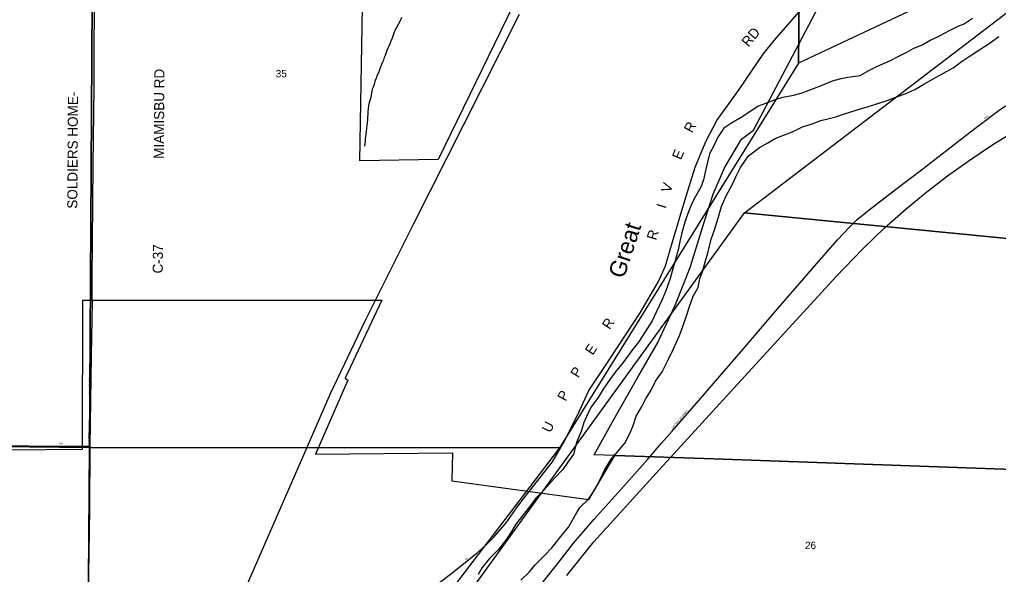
# Model space of a CAD drawing. Extents: x 1312308 to 1684953, y 460642 to 865172.
# Drawn here: x 1464004 to 1471284, y 608140 to 612264 of the extents above; entities that cross this region are included whole.
import ezdxf

# ---------------------------------------------------------------- set-up
doc = ezdxf.new("R2010")
doc.units = 0
for name, color, linetype in [('GM_X_City_Street', 7, 'Continuous'), ('GM_X_City_Street_Text', 7, 'Continuous'), ('GM_X_Corporation', 7, 'Continuous'), ('GM_X_County_Road', 7, 'Continuous'), ('GM_X_County_Road_Text', 7, 'Continuous'), ('GM_X_Major_River', 7, 'Continuous'), ('GM_X_Major_River_Text', 7, 'Continuous'), ('GM_X_Minor_River', 7, 'Continuous'), ('GM_X_Rail_Line', 7, 'Continuous'), ('GM_X_Section', 7, 'Continuous'), ('GM_X_Section_Text', 7, 'Continuous')]:
    doc.layers.add(name, color=color, linetype=linetype)

msp = doc.modelspace()

# ---------------------------------------------------------------- linework, layer by layer
at = {"layer": 'GM_X_City_Street'}
for points in [[(1468857.5, 609205.9), (1468922.5, 609280.2), (1469070, 609450.8), (1469369.5, 609797.7), (1469644.3, 610117), (1469901.1, 610412.6), (1470086.9, 610626), (1470175.3, 610720.6), (1470233.3, 610776.9), (1470322.8, 610850.6), (1470517.6, 611000.4), (1470721.5, 611155.2), (1470954.6, 611334.3), (1471108.3, 611453.7), (1471298.1, 611597.3), (1471392.1, 611654.7), (1471438, 611679.2)], [(1464529.3, 609093.2), (1464540.1, 609768.4), (1464545.7, 610167.5), (1464545.4, 610198.9)], [(1466565.6, 606437.4), (1466577.3, 606455.8), (1466697.1, 606611.8), (1466965.8, 606937.8), (1467267.6, 607305), (1467514.2, 607608.5), (1467683.2, 607814.5), (1467782.2, 607939), (1468014.2, 608232.3), (1468124, 608373.1), (1468277.3, 608551.9), (1468477.6, 608774.6), (1468675.8, 608997), (1468777.7, 609114.7), (1468857.5, 609205.9)], [(1463608.6, 609099), (1464529.3, 609093.2)], [(1464564.1, 606661.8), (1464564.3, 606675.3), (1464562.8, 606850.2), (1464561.4, 606908.5), (1464558.5, 606987.9), (1464519.1, 607613.2), (1464517.6, 607859.4), (1464518.2, 607956.2), (1464519.8, 608142.9), (1464527.1, 608625.3), (1464529.3, 609093.2)], [(1466939, 607935.5), (1467208.6, 608141.5), (1467405.1, 608297.9), (1467476.7, 608363.1), (1467530.1, 608417.4), (1467622.1, 608524.2), (1467710.9, 608646.9), (1467794.8, 608756.9)]]:
    msp.add_lwpolyline(points, dxfattribs=at)
at = {"layer": 'GM_X_Corporation'}
for points in [[(1468000.8, 613036.8), (1467116.7, 611223.9), (1466533.9, 611213.7), (1466573.9, 613505.6)], [(1471462.7, 608917.9), (1469167.1, 608998), (1468430.5, 609023.7), (1468277.6, 609029), (1468425.5, 609297.4), (1468602.4, 609606.8), (1468747.4, 609859), (1468883.4, 610145.6), (1468990.9, 610421.1), (1469083.1, 610719.2), (1469163.6, 610967.4), (1469246.3, 611161.5), (1469372, 611376.2), (1469462.4, 611441.1), (1470092.7, 612637.7)], [(1463660, 609064.6), (1464473.2, 609070.1), (1464474.7, 610177.3), (1466698.1, 610178.1), (1466425.2, 609599), (1466446.5, 609583.7), (1466205.4, 609032.9), (1467224.2, 609044.8), (1467218.2, 608836.1), (1468237.8, 608696), (1468430.5, 609023.7), (1469167.1, 608998), (1471462.7, 608917.9)]]:
    msp.add_lwpolyline(points, dxfattribs=at)
at = {"layer": 'GM_X_County_Road'}
for points in [[(1464545.4, 610198.9), (1464544.1, 610333.3), (1464552, 611181.8), (1464559.2, 611763.4), (1464560.8, 612618.4), (1464564.8, 613141), (1464569.5, 613788), (1464569.8, 614464.2)], [(1467794.8, 608756.9), (1467966.5, 608977.6), (1468060.2, 609136), (1468167.4, 609356.1), (1468236.9, 609507), (1468392.3, 609738.2), (1468620.5, 610084), (1468756, 610317.6), (1468808.7, 610434.7), (1468860.8, 610612), (1468951.9, 610918.8), (1469027.6, 611167.8), (1469110.2, 611362.5), (1469189.7, 611513.1), (1469355.2, 611744.1), (1469533.4, 612006.8), (1469615.8, 612109.3), (1469800.9, 612321.8)]]:
    msp.add_lwpolyline(points, dxfattribs=at)
at = {"layer": 'GM_X_Major_River'}
for points in [[(1471091.1, 612272.2), (1471032, 612233.2), (1470977.3, 612210.2), (1470916.4, 612179.3), (1470849.3, 612142.5), (1470780.3, 612109.8), (1470721.3, 612076.8), (1470652.4, 612048), (1470599.5, 612019), (1470536.6, 611986.1), (1470479.7, 611957.1), (1470427, 611934.1), (1470376.3, 611913), (1470317.4, 611884), (1470252.3, 611845.2), (1470163.6, 611832.9), (1470101, 611820), (1470048.5, 611805), (1469969.5, 611774.5), (1469892.5, 611743.9), (1469815.5, 611715.3), (1469746.8, 611696.6), (1469680.2, 611683.8), (1469627.7, 611670.8), (1469550.7, 611640.2), (1469496, 611619.2), (1469428.7, 611574.4), (1469369.7, 611535.4), (1469294.4, 611492.8), (1469241.4, 611457.7), (1469197.9, 611390.3), (1469170.5, 611330.6), (1469135, 611265.1), (1469119.7, 611203.2), (1469108.6, 611151.3), (1469090.9, 611073.4), (1469069.7, 611017.6), (1469032.1, 610948.1), (1469004.9, 610896.4), (1468973.2, 610822.8), (1468951.8, 610759), (1468930.1, 610679.2), (1468914.7, 610615.3), (1468901.4, 610551.4), (1468877.5, 610463.5), (1468857.9, 610393.7), (1468842.8, 610339.8), (1468810.8, 610248.2), (1468783.3, 610182.5), (1468741.3, 610093), (1468707.7, 610025.4), (1468655.8, 609942.2), (1468608, 609866.9), (1468556.5, 609803.7), (1468521.3, 609752.2), (1468480, 609700.9), (1468432.6, 609643.6), (1468393.3, 609588.2), (1468343.6, 609516.9), (1468306.2, 609455.5), (1468258.6, 609388.2), (1468231.4, 609336.6), (1468199.9, 609269), (1468180.4, 609203.1), (1468146.6, 609121.5), (1468122.7, 609033.7), (1468081.3, 608974.3), (1468044, 608920.9), (1467980.3, 608851.9), (1467902.2, 608765.2), (1467844.7, 608706.1), (1467797.2, 608642.9), (1467749.7, 608583.6), (1467696, 608512.4), (1467654.5, 608447), (1467621.3, 608395.5), (1467563.5, 608322.4), (1467499.9, 608259.5), (1467444.3, 608192.3), (1467415, 608138.8)], [(1469050.4, 610271.5), (1469063.9, 610339.5), (1469085.1, 610395.3), (1469102.6, 610463.1), (1469126.2, 610538.9), (1469148.2, 610632.8), (1469171.7, 610700.5), (1469195.3, 610772.3), (1469223.5, 610874.1), (1469257.2, 610949.7), (1469305.3, 611041.1), (1469330.5, 611094.7), (1469366.1, 611164.3), (1469424.2, 611251.4), (1469505.8, 611312), (1469568.8, 611346.9), (1469623.8, 611379.9), (1469692.6, 611406.7), (1469751.4, 611429.6), (1469826.5, 611466.2), (1469899.3, 611488.9), (1469964.1, 611513.7), (1470014.7, 611526.8), (1470075.3, 611541.6), (1470138, 611564.5), (1470265.5, 611604.1), (1470324.1, 611621), (1470386.8, 611639.9), (1470455.6, 611662.6), (1470532.6, 611693.2), (1470591.3, 611712.1), (1470662.3, 611744.8), (1470733.5, 611785.6), (1470814.9, 611834.2), (1470875.8, 611865.1), (1470947, 611905.8), (1471006.1, 611948.8), (1471073.4, 611993.6), (1471144.7, 612040.4), (1471214, 612087.2), (1471287.4, 612137.9)], [(1467731.8, 608098.4), (1467795.3, 608157.4), (1467838.6, 608210.7), (1467910.4, 608283.5), (1467963.8, 608338.6), (1468029.8, 608421.6), (1468085.5, 608490.7), (1468139.6, 608582), (1468170.9, 608637.5), (1468234.5, 608700.5), (1468280, 608765.8), (1468317.6, 608835.3), (1468357.5, 608918.8), (1468403.3, 608996.1), (1468452.7, 609053.3), (1468504.3, 609116.5), (1468546, 609191.9), (1468567.2, 609247.7), (1468590.8, 609317.5), (1468628.3, 609382.9), (1468659.6, 609442.5), (1468701.2, 609509.9), (1468734.7, 609575.5), (1468784.4, 609646.7), (1468830.5, 609740.1), (1468868.3, 609815.6), (1468912.5, 609915.1), (1468936, 609982.8), (1468965.9, 610070.5), (1468987.3, 610132.3), (1469014.9, 610208), (1469050.4, 610271.5)]]:
    msp.add_lwpolyline(points, dxfattribs=at)
at = {"layer": 'GM_X_Minor_River'}
msp.add_lwpolyline([(1466844.7, 612279.4), (1466836.2, 612259.5), (1466804.4, 612199.9), (1466795.9, 612182), (1466787.3, 612162.1), (1466774.3, 612126.2), (1466765.7, 612104.3), (1466757.2, 612084.4), (1466750.7, 612066.5), (1466744.2, 612050.6), (1466733.5, 612026.7), (1466729.1, 612010.7), (1466722.7, 611996.8), (1466716.2, 611980.9), (1466709.7, 611962.9), (1466703.3, 611947), (1466696.8, 611929.1), (1466688.3, 611911.2), (1466681.7, 611891.2), (1466673.1, 611869.3), (1466662.4, 611845.4), (1466655.9, 611825.5), (1466647.4, 611807.6), (1466642.9, 611789.6), (1466634.1, 611761.7), (1466627.6, 611745.8), (1466623.3, 611731.8), (1466618.6, 611705.8), (1466616, 611685.7), (1466611.6, 611669.7), (1466605, 611647.8), (1466600.4, 611625.8), (1466597.7, 611599.7), (1466595.2, 611581.7), (1466594.7, 611559.6), (1466592.2, 611541.5), (1466591.7, 611521.4), (1466589, 611497.4), (1466584, 611457.3), (1466581.3, 611433.2), (1466578.8, 611413.2), (1466576.3, 611395.1), (1466573.9, 611379.1), (1466573.4, 611361), (1466571, 611345), (1466568.4, 611322.9)], dxfattribs=at)
at = {"layer": 'GM_X_Rail_Line'}
for points in [[(1463785.4, 603708.8), (1464304.5, 604888.8), (1464631.1, 605630.2), (1464981.7, 606433.1), (1465598.2, 607838), (1466136.9, 609068.4), (1466317.3, 609485.7), (1466575.5, 610025.2), (1466934.6, 610742.6), (1467308.3, 611484), (1467722.2, 612304.8)], [(1468073.3, 608132.5), (1468212.9, 608306.2), (1468276, 608381.6), (1468762.4, 608918.8), (1469396.8, 609612.4), (1470078.1, 610354), (1470276.4, 610560.6), (1470435, 610712.5), (1470597.5, 610857.7), (1470740.1, 610973.6), (1470905.7, 611102.8), (1471066, 611217.3), (1471249.7, 611340.2), (1471486.5, 611483.1)]]:
    msp.add_lwpolyline(points, dxfattribs=at)
at = {"layer": 'GM_X_Section'}
for points in [[(1459323.4, 614534.3), (1464555.5, 614469.2), (1464523.3, 609084.4), (1459175.1, 609143.8)], [(1464555.5, 614469.2), (1469822.5, 614451.4), (1469796.1, 611940.2), (1468020.8, 609080.2), (1464523.3, 609084.4)], [(1469822.5, 614451.4), (1472463.7, 614424.4), (1471829.1, 612897.3), (1469796.1, 611940.2)], [(1469395.8, 610826.4), (1472492.9, 613193.9), (1472263.8, 610546.9)], [(1469395.8, 610826.4), (1472263.8, 610546.9), (1471778.4, 605097.2), (1466205.4, 605615), (1466316.8, 606578.7)], [(1459175.1, 609143.8), (1464523.3, 609084.4), (1464490.4, 604455.6), (1463462, 603736.3), (1459107.6, 603789.7)], [(1464523.3, 609084.4), (1468020.8, 609080.2), (1464490.4, 604455.6)]]:
    msp.add_lwpolyline(points, close=True, dxfattribs=at)

# ---------------------------------------------------------------- texts
at = {"layer": 'GM_X_City_Street_Text'}
for s, rotation, p in [('PIKE', 37.23328, (1471181.6, 611520.7)), ('RD', 90, (1464538.3, 610100.9)), ('HOME-MIAMISBU', 89.09826, (1464529.5, 609471.8)), ('DAYTON-CINCINNATI', 49.22691, (1468861.4, 609222.6)), ('SOLDIERS', 89.13239, (1464525.1, 609111)), ('RD', 0.00001, (1464301.3, 609107.1)), ('RD', 40.60386, (1467322.4, 608242.4))]:
    msp.add_text(s, height=12.5, rotation=rotation, dxfattribs=at).set_placement(p)
at = {"layer": 'GM_X_County_Road_Text'}
for s, rotation, p in [('RD', 50.37259, (1469424.7, 612055.4)), ('MIAMISBU RD', 89.69507, (1465077.7, 611229.2)), ('SOLDIERS HOME-', 89.66994, (1464433.9, 610858.3)), ('R', 60.48215, (1469005.5, 611415)), ('E', 67.19981, (1468922.7, 611216.5)), ('V', 72.27697, (1468844.7, 610971.6)), ('I', 73.1228, (1468809.3, 610854.8)), ('R', 73.13888, (1468737.9, 610619)), ('C-37', 89.31291, (1465068.9, 610376.2)), ('R', 56.88289, (1468393.3, 609954.5)), ('E', 56.14352, (1468266, 609764.7)), ('P', 57.72668, (1468159.1, 609595.4)), ('P', 61.48396, (1468065.1, 609422)), ('U', 64.243, (1467952.1, 609187.7))]:
    msp.add_text(s, height=75, rotation=rotation, dxfattribs=at).set_placement(p)
at = {"layer": 'GM_X_Major_River_Text'}
msp.add_text('Great', height=124.99, rotation=71.78433, dxfattribs=at).set_placement((1468498.5, 610332.5))
at = {"layer": 'GM_X_Section_Text'}
for s, p in [('35', (1465909.5, 611834.8)), ('26', (1469845.3, 608328))]:
    msp.add_text(s, height=55.25, rotation=0.00001, dxfattribs=at).set_placement(p)

doc.saveas('drawing.dxf')
